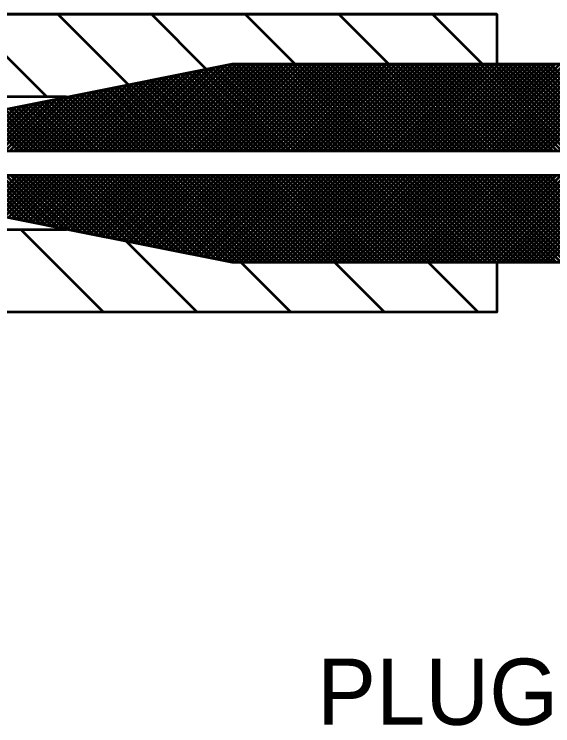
# Model space of a CAD drawing. Extents: x -32 to 824, y -6 to 538.
# Drawn here: x 183.94 to 203.45, y 439.33 to 465.12 of the extents above; entities that cross this region are included whole.
import ezdxf

# ---------------------------------------------------------------- set-up
doc = ezdxf.new("R2010")
doc.units = 0
doc.header["$LTSCALE"] = 1.1
doc.layers.add('1', color=7, linetype='Continuous', lineweight=53)

msp = doc.modelspace()

# ---------------------------------------------------------------- linework, layer by layer
at = {"layer": '1'}
for p, q in [((201.43, 465.121), (169.71, 465.121)), ((185.121, 462.121), (182.121, 465.121)), ((188.067, 462.569), (185.515, 465.121)), ((190.896, 463.134), (188.909, 465.121)), ((194.103, 463.321), (192.303, 465.121)), ((197.497, 463.321), (195.697, 465.121)), ((200.891, 463.321), (199.091, 465.121)), ((188.355, 460.171), (191.423, 463.24)), ((188.524, 460.171), (191.635, 463.282)), ((188.694, 460.171), (191.844, 463.321)), ((188.864, 460.171), (192.014, 463.321)), ((189.033, 460.171), (192.183, 463.321)), ((189.203, 460.171), (192.353, 463.321)), ((189.373, 460.171), (192.523, 463.321)), ((189.543, 460.171), (192.692, 463.321)), ((189.712, 460.171), (192.862, 463.321)), ((189.882, 460.171), (193.032, 463.321)), ((190.052, 460.171), (193.202, 463.321)), ((190.221, 460.171), (193.371, 463.321)), ((190.391, 460.171), (193.541, 463.321)), ((190.561, 460.171), (193.711, 463.321)), ((190.73, 460.171), (193.88, 463.321)), ((190.9, 460.171), (194.05, 463.321)), ((191.07, 460.171), (194.22, 463.321)), ((191.24, 460.171), (194.389, 463.321)), ((194.451, 460.171), (191.389, 463.233)), ((191.409, 460.171), (194.559, 463.321)), ((194.621, 460.171), (191.531, 463.261)), ((191.579, 460.171), (194.729, 463.321)), ((194.791, 460.171), (191.672, 463.29)), ((191.749, 460.171), (194.899, 463.321)), ((194.96, 460.171), (191.814, 463.318)), ((191.918, 460.171), (195.068, 463.321)), ((195.13, 460.171), (191.98, 463.321)), ((192.088, 460.171), (195.238, 463.321)), ((195.3, 460.171), (192.15, 463.321)), ((192.258, 460.171), (195.408, 463.321)), ((195.47, 460.171), (192.32, 463.321)), ((192.428, 460.171), (195.578, 463.321)), ((195.639, 460.171), (192.489, 463.321)), ((192.597, 460.171), (195.747, 463.321)), ((195.809, 460.171), (192.659, 463.321)), ((192.767, 460.171), (195.917, 463.321)), ((195.979, 460.171), (192.829, 463.321)), ((192.937, 460.171), (196.087, 463.321)), ((196.148, 460.171), (192.998, 463.321)), ((193.106, 460.171), (196.256, 463.321)), ((196.318, 460.171), (193.168, 463.321)), ((193.276, 460.171), (196.426, 463.321)), ((196.488, 460.171), (193.338, 463.321)), ((193.446, 460.171), (196.596, 463.321)), ((196.657, 460.171), (193.507, 463.321)), ((193.615, 460.171), (196.765, 463.321)), ((196.827, 460.171), (193.677, 463.321)), ((193.785, 460.171), (196.935, 463.321)), ((196.997, 460.171), (193.847, 463.321)), ((193.955, 460.171), (197.105, 463.321)), ((197.167, 460.171), (194.017, 463.321)), ((194.125, 460.171), (197.275, 463.321)), ((197.336, 460.171), (194.186, 463.321)), ((194.294, 460.171), (197.444, 463.321)), ((197.506, 460.171), (194.356, 463.321)), ((194.464, 460.171), (197.614, 463.321)), ((197.676, 460.171), (194.526, 463.321)), ((194.634, 460.171), (197.784, 463.321)), ((197.845, 460.171), (194.695, 463.321)), ((194.803, 460.171), (197.953, 463.321)), ((198.015, 460.171), (194.865, 463.321)), ((194.973, 460.171), (198.123, 463.321)), ((198.185, 460.171), (195.035, 463.321)), ((195.143, 460.171), (198.293, 463.321)), ((198.355, 460.171), (195.204, 463.321)), ((195.312, 460.171), (198.463, 463.321)), ((198.524, 460.171), (195.374, 463.321)), ((195.482, 460.171), (198.632, 463.321)), ((198.694, 460.171), (195.544, 463.321)), ((195.652, 460.171), (198.802, 463.321)), ((198.864, 460.171), (195.714, 463.321)), ((195.822, 460.171), (198.972, 463.321)), ((199.033, 460.171), (195.883, 463.321)), ((195.991, 460.171), (199.141, 463.321)), ((199.203, 460.171), (196.053, 463.321)), ((196.161, 460.171), (199.311, 463.321)), ((199.373, 460.171), (196.223, 463.321)), ((196.331, 460.171), (199.481, 463.321)), ((199.542, 460.171), (196.392, 463.321)), ((196.5, 460.171), (199.65, 463.321)), ((199.712, 460.171), (196.562, 463.321)), ((196.67, 460.171), (199.82, 463.321)), ((199.882, 460.171), (196.732, 463.321)), ((196.84, 460.171), (199.99, 463.321)), ((200.052, 460.171), (196.901, 463.321)), ((197.01, 460.171), (200.16, 463.321)), ((200.221, 460.171), (197.071, 463.321)), ((197.179, 460.171), (200.329, 463.321)), ((200.391, 460.171), (197.241, 463.321)), ((197.349, 460.171), (200.499, 463.321)), ((200.561, 460.171), (197.411, 463.321)), ((197.519, 460.171), (200.669, 463.321)), ((200.73, 460.171), (197.58, 463.321)), ((197.688, 460.171), (200.838, 463.321)), ((200.9, 460.171), (197.75, 463.321)), ((197.858, 460.171), (201.008, 463.321)), ((201.07, 460.171), (197.92, 463.321)), ((198.028, 460.171), (201.178, 463.321)), ((201.239, 460.171), (198.089, 463.321)), ((198.198, 460.171), (201.347, 463.321)), ((201.409, 460.171), (198.259, 463.321)), ((198.367, 460.171), (201.517, 463.321)), ((201.579, 460.171), (198.429, 463.321)), ((198.537, 460.171), (201.687, 463.321)), ((201.749, 460.171), (198.599, 463.321)), ((198.707, 460.171), (201.857, 463.321)), ((201.918, 460.171), (198.768, 463.321)), ((198.876, 460.171), (202.026, 463.321)), ((202.088, 460.171), (198.938, 463.321)), ((199.046, 460.171), (202.196, 463.321)), ((202.258, 460.171), (199.108, 463.321)), ((199.216, 460.171), (202.366, 463.321)), ((202.427, 460.171), (199.277, 463.321)), ((199.385, 460.171), (202.535, 463.321)), ((202.597, 460.171), (199.447, 463.321)), ((199.555, 460.171), (202.705, 463.321)), ((202.767, 460.171), (199.617, 463.321)), ((199.725, 460.171), (202.875, 463.321)), ((202.937, 460.171), (199.787, 463.321)), ((199.895, 460.171), (203.044, 463.321)), ((203.106, 460.171), (199.956, 463.321)), ((200.064, 460.171), (203.214, 463.321)), ((203.276, 460.171), (200.126, 463.321)), ((200.234, 460.171), (203.384, 463.321)), ((203.446, 460.171), (200.296, 463.321)), ((200.404, 460.171), (203.554, 463.321)), ((203.615, 460.171), (200.465, 463.321)), ((200.573, 460.171), (203.723, 463.321)), ((203.785, 460.171), (200.635, 463.321)), ((200.743, 460.171), (203.893, 463.321)), ((203.955, 460.171), (200.805, 463.321)), ((200.913, 460.171), (204.063, 463.321)), ((204.124, 460.171), (200.974, 463.321)), ((201.083, 460.171), (204.233, 463.321)), ((204.294, 460.171), (201.144, 463.321)), ((201.252, 460.171), (204.402, 463.321)), ((204.464, 460.171), (201.314, 463.321)), ((201.422, 460.171), (204.572, 463.321)), ((204.634, 460.171), (201.484, 463.321)), ((201.592, 460.171), (204.742, 463.321)), ((204.803, 460.171), (201.653, 463.321)), ((201.761, 460.171), (204.911, 463.321)), ((204.973, 460.171), (201.823, 463.321)), ((201.931, 460.171), (205.081, 463.321)), ((205.143, 460.171), (201.993, 463.321)), ((202.067, 463.275), (202.02, 463.321)), ((202.101, 460.171), (205.251, 463.321)), ((205.312, 460.171), (202.162, 463.321)), ((202.236, 463.275), (202.189, 463.321)), ((202.27, 460.171), (205.42, 463.321)), ((205.482, 460.171), (202.332, 463.321)), ((202.406, 463.275), (202.359, 463.321)), ((202.44, 460.171), (205.59, 463.321)), ((205.652, 460.171), (202.502, 463.321)), ((202.576, 463.275), (202.529, 463.321)), ((202.61, 460.171), (205.76, 463.321)), ((205.822, 460.171), (202.672, 463.321)), ((202.745, 463.275), (202.698, 463.321)), ((202.78, 460.171), (205.93, 463.321)), ((205.991, 460.171), (202.841, 463.321)), ((202.915, 463.275), (202.868, 463.321)), ((202.949, 460.171), (206.099, 463.321)), ((206.161, 460.171), (203.011, 463.321)), ((203.085, 463.275), (203.038, 463.321)), ((203.119, 460.171), (206.269, 463.321)), ((206.331, 460.171), (203.181, 463.321)), ((203.254, 463.275), (203.208, 463.321)), ((203.289, 460.171), (206.439, 463.321)), ((206.5, 460.171), (203.35, 463.321)), ((203.424, 463.275), (203.377, 463.321)), ((187.336, 460.171), (190.15, 462.985)), ((187.506, 460.171), (190.362, 463.028)), ((187.676, 460.171), (190.575, 463.07)), ((187.845, 460.171), (190.787, 463.113)), ((188.015, 460.171), (190.999, 463.155)), ((188.185, 460.171), (191.211, 463.197)), ((192.754, 460.171), (189.975, 462.95)), ((192.924, 460.171), (190.117, 462.978)), ((193.094, 460.171), (190.258, 463.007)), ((193.263, 460.171), (190.4, 463.035)), ((193.433, 460.171), (190.541, 463.063)), ((193.603, 460.171), (190.682, 463.092)), ((193.772, 460.171), (190.824, 463.12)), ((193.942, 460.171), (190.965, 463.148)), ((194.112, 460.171), (191.107, 463.177)), ((194.282, 460.171), (191.248, 463.205)), ((186.318, 460.171), (188.877, 462.731)), ((186.488, 460.171), (189.09, 462.773)), ((186.657, 460.171), (189.302, 462.816)), ((186.827, 460.171), (189.514, 462.858)), ((186.997, 460.171), (189.726, 462.9)), ((187.167, 460.171), (189.938, 462.943)), ((191.227, 460.171), (188.702, 462.696)), ((191.397, 460.171), (188.844, 462.724)), ((191.566, 460.171), (188.985, 462.752)), ((191.736, 460.171), (189.127, 462.781)), ((191.906, 460.171), (189.268, 462.809)), ((192.075, 460.171), (189.41, 462.837)), ((192.245, 460.171), (189.551, 462.865)), ((192.415, 460.171), (189.692, 462.894)), ((192.585, 460.171), (189.834, 462.922)), ((185.13, 460.171), (187.393, 462.434)), ((185.3, 460.171), (187.605, 462.476)), ((185.47, 460.171), (187.817, 462.519)), ((185.639, 460.171), (188.029, 462.561)), ((185.809, 460.171), (188.241, 462.603)), ((185.979, 460.171), (188.453, 462.646)), ((186.148, 460.171), (188.665, 462.688)), ((189.7, 460.171), (187.43, 462.441)), ((189.869, 460.171), (187.571, 462.469)), ((190.039, 460.171), (187.713, 462.498)), ((190.209, 460.171), (187.854, 462.526)), ((190.378, 460.171), (187.995, 462.554)), ((190.548, 460.171), (188.137, 462.583)), ((190.718, 460.171), (188.278, 462.611)), ((190.887, 460.171), (188.42, 462.639)), ((191.057, 460.171), (188.561, 462.667)), ((184.112, 460.171), (186.12, 462.179)), ((184.282, 460.171), (186.332, 462.222)), ((184.451, 460.171), (186.544, 462.264)), ((184.621, 460.171), (186.756, 462.307)), ((184.791, 460.171), (186.968, 462.349)), ((184.96, 460.171), (187.18, 462.391)), ((188.172, 460.171), (186.157, 462.187)), ((188.342, 460.171), (186.298, 462.215)), ((188.512, 460.171), (186.44, 462.243)), ((188.681, 460.171), (186.581, 462.271)), ((188.851, 460.171), (186.722, 462.3)), ((189.021, 460.171), (186.864, 462.328)), ((189.19, 460.171), (187.005, 462.356)), ((189.36, 460.171), (187.147, 462.385)), ((189.53, 460.171), (187.288, 462.413)), ((183.094, 460.171), (184.847, 461.925)), ((183.263, 460.171), (185.059, 461.967)), ((183.433, 460.171), (185.271, 462.01)), ((183.603, 460.171), (185.483, 462.052)), ((183.773, 460.171), (185.696, 462.094)), ((183.942, 460.171), (185.908, 462.137)), ((186.645, 460.171), (184.884, 461.932)), ((186.815, 460.171), (185.026, 461.96)), ((186.984, 460.171), (185.167, 461.989)), ((187.154, 460.171), (185.308, 462.017)), ((187.324, 460.171), (185.45, 462.045)), ((187.493, 460.171), (185.591, 462.073)), ((187.663, 460.171), (185.733, 462.102)), ((187.833, 460.171), (185.874, 462.13)), ((188.002, 460.171), (186.015, 462.158)), ((182.415, 460.171), (183.998, 461.755)), ((182.585, 460.171), (184.211, 461.797)), ((182.754, 460.171), (184.423, 461.84)), ((182.924, 460.171), (184.635, 461.882)), ((185.117, 460.171), (183.611, 461.678)), ((185.287, 460.171), (183.753, 461.706)), ((185.457, 460.171), (183.894, 461.734)), ((185.627, 460.171), (184.036, 461.762)), ((185.796, 460.171), (184.177, 461.791)), ((185.966, 460.171), (184.318, 461.819)), ((186.136, 460.171), (184.46, 461.847)), ((186.305, 460.171), (184.601, 461.876)), ((186.475, 460.171), (184.743, 461.904)), ((184.099, 460.171), (182.763, 461.508)), ((184.269, 460.171), (182.904, 461.536)), ((184.439, 460.171), (183.046, 461.564)), ((184.608, 460.171), (183.187, 461.593)), ((184.778, 460.171), (183.328, 461.621)), ((184.948, 460.171), (183.47, 461.649)), ((184.047, 457.678), (182.454, 459.271)), ((184.259, 457.636), (182.623, 459.271)), ((182.73, 457.941), (184.06, 459.271)), ((184.471, 457.593), (182.793, 459.271)), ((182.872, 457.913), (184.23, 459.271)), ((184.683, 457.551), (182.963, 459.271)), ((183.013, 457.885), (184.4, 459.271)), ((184.895, 457.508), (183.132, 459.271)), ((183.155, 457.856), (184.57, 459.271)), ((183.296, 457.828), (184.739, 459.271)), ((185.108, 457.466), (183.302, 459.271)), ((183.438, 457.8), (184.909, 459.271)), ((185.32, 457.423), (183.472, 459.271)), ((183.579, 457.772), (185.079, 459.271)), ((185.532, 457.381), (183.642, 459.271)), ((183.72, 457.743), (185.248, 459.271)), ((185.744, 457.339), (183.811, 459.271)), ((183.862, 457.715), (185.418, 459.271)), ((185.956, 457.296), (183.981, 459.271)), ((184.003, 457.687), (185.588, 459.271)), ((184.145, 457.658), (185.758, 459.271)), ((186.168, 457.254), (184.151, 459.271)), ((184.286, 457.63), (185.927, 459.271)), ((186.38, 457.211), (184.32, 459.271)), ((184.427, 457.602), (186.097, 459.271)), ((186.593, 457.169), (184.49, 459.271)), ((184.569, 457.574), (186.267, 459.271)), ((186.805, 457.126), (184.66, 459.271)), ((184.71, 457.545), (186.436, 459.271)), ((187.017, 457.084), (184.829, 459.271)), ((184.852, 457.517), (186.606, 459.271)), ((184.993, 457.489), (186.776, 459.271)), ((187.229, 457.042), (184.999, 459.271)), ((185.135, 457.46), (186.945, 459.271)), ((187.441, 456.999), (185.169, 459.271)), ((185.276, 457.432), (187.115, 459.271)), ((187.653, 456.957), (185.339, 459.271)), ((185.417, 457.404), (187.285, 459.271)), ((187.865, 456.914), (185.508, 459.271)), ((185.559, 457.376), (187.454, 459.271)), ((188.077, 456.872), (185.678, 459.271)), ((185.7, 457.347), (187.624, 459.271)), ((185.842, 457.319), (187.794, 459.271)), ((188.29, 456.829), (185.848, 459.271)), ((185.983, 457.291), (187.964, 459.271)), ((188.502, 456.787), (186.017, 459.271)), ((186.125, 457.262), (188.133, 459.271)), ((188.714, 456.745), (186.187, 459.271)), ((186.266, 457.234), (188.303, 459.271)), ((188.926, 456.702), (186.357, 459.271)), ((186.407, 457.206), (188.473, 459.271)), ((189.138, 456.66), (186.526, 459.271)), ((186.549, 457.178), (188.643, 459.271)), ((186.69, 457.149), (188.812, 459.271)), ((189.35, 456.617), (186.696, 459.271)), ((186.832, 457.121), (188.982, 459.271)), ((189.562, 456.575), (186.866, 459.271)), ((186.973, 457.093), (189.152, 459.271)), ((189.775, 456.533), (187.036, 459.271)), ((187.115, 457.065), (189.321, 459.271)), ((189.987, 456.49), (187.205, 459.271)), ((187.256, 457.036), (189.491, 459.271)), ((190.199, 456.448), (187.375, 459.271)), ((187.397, 457.008), (189.661, 459.271)), ((187.539, 456.98), (189.83, 459.271)), ((190.411, 456.405), (187.545, 459.271)), ((187.68, 456.951), (190, 459.271)), ((190.623, 456.363), (187.715, 459.271)), ((187.822, 456.923), (190.17, 459.271)), ((190.835, 456.32), (187.884, 459.271)), ((187.963, 456.895), (190.34, 459.271)), ((191.047, 456.278), (188.054, 459.271)), ((188.104, 456.867), (190.509, 459.271)), ((191.259, 456.236), (188.224, 459.271)), ((188.246, 456.838), (190.679, 459.271)), ((188.387, 456.81), (190.849, 459.271)), ((191.472, 456.193), (188.393, 459.271)), ((188.529, 456.782), (191.018, 459.271)), ((191.684, 456.151), (188.563, 459.271)), ((188.67, 456.753), (191.188, 459.271)), ((191.883, 456.121), (188.733, 459.271)), ((188.811, 456.725), (191.358, 459.271)), ((192.052, 456.121), (188.902, 459.271)), ((188.953, 456.697), (191.528, 459.271)), ((192.222, 456.121), (189.072, 459.271)), ((189.094, 456.668), (191.697, 459.271)), ((189.236, 456.64), (191.867, 459.271)), ((192.392, 456.121), (189.242, 459.271)), ((189.377, 456.612), (192.037, 459.271)), ((192.561, 456.121), (189.412, 459.271)), ((189.519, 456.584), (192.206, 459.271)), ((192.731, 456.121), (189.581, 459.271)), ((189.66, 456.555), (192.376, 459.271)), ((192.901, 456.121), (189.751, 459.271)), ((189.802, 456.527), (192.546, 459.271)), ((193.071, 456.121), (189.921, 459.271)), ((189.943, 456.499), (192.715, 459.271)), ((190.084, 456.471), (192.885, 459.271)), ((193.24, 456.121), (190.09, 459.271)), ((190.226, 456.442), (193.055, 459.271)), ((193.41, 456.121), (190.26, 459.271)), ((190.367, 456.414), (193.225, 459.271)), ((193.58, 456.121), (190.43, 459.271)), ((190.509, 456.386), (193.394, 459.271)), ((193.75, 456.121), (190.6, 459.271)), ((190.65, 456.357), (193.564, 459.271)), ((193.919, 456.121), (190.769, 459.271)), ((190.791, 456.329), (193.734, 459.271)), ((190.933, 456.301), (193.903, 459.271)), ((194.089, 456.121), (190.939, 459.271)), ((191.074, 456.273), (194.073, 459.271)), ((194.259, 456.121), (191.109, 459.271)), ((191.216, 456.244), (194.243, 459.271)), ((194.428, 456.121), (191.278, 459.271)), ((191.357, 456.216), (194.413, 459.271)), ((194.598, 456.121), (191.448, 459.271)), ((191.499, 456.188), (194.582, 459.271)), ((194.768, 456.121), (191.618, 459.271)), ((191.64, 456.159), (194.752, 459.271)), ((191.781, 456.131), (194.922, 459.271)), ((194.937, 456.121), (191.787, 459.271)), ((191.941, 456.121), (195.091, 459.271)), ((195.107, 456.121), (191.957, 459.271)), ((192.111, 456.121), (195.261, 459.271)), ((195.277, 456.121), (192.127, 459.271)), ((192.281, 456.121), (195.431, 459.271)), ((195.447, 456.121), (192.297, 459.271)), ((192.45, 456.121), (195.6, 459.271)), ((195.616, 456.121), (192.466, 459.271)), ((192.62, 456.121), (195.77, 459.271)), ((195.786, 456.121), (192.636, 459.271)), ((192.79, 456.121), (195.94, 459.271)), ((195.956, 456.121), (192.806, 459.271)), ((192.96, 456.121), (196.109, 459.271)), ((196.125, 456.121), (192.975, 459.271)), ((193.129, 456.121), (196.279, 459.271)), ((196.295, 456.121), (193.145, 459.271)), ((193.299, 456.121), (196.449, 459.271)), ((196.465, 456.121), (193.315, 459.271)), ((193.469, 456.121), (196.619, 459.271)), ((196.635, 456.121), (193.484, 459.271)), ((193.638, 456.121), (196.788, 459.271)), ((196.804, 456.121), (193.654, 459.271)), ((193.808, 456.121), (196.958, 459.271)), ((196.974, 456.121), (193.824, 459.271)), ((193.978, 456.121), (197.128, 459.271)), ((197.144, 456.121), (193.994, 459.271)), ((194.148, 456.121), (197.298, 459.271)), ((197.313, 456.121), (194.163, 459.271)), ((194.317, 456.121), (197.467, 459.271)), ((197.483, 456.121), (194.333, 459.271)), ((194.487, 456.121), (197.637, 459.271)), ((197.653, 456.121), (194.503, 459.271)), ((194.657, 456.121), (197.807, 459.271)), ((197.822, 456.121), (194.672, 459.271)), ((194.826, 456.121), (197.976, 459.271)), ((197.992, 456.121), (194.842, 459.271)), ((194.996, 456.121), (198.146, 459.271)), ((198.162, 456.121), (195.012, 459.271)), ((195.166, 456.121), (198.316, 459.271)), ((198.332, 456.121), (195.181, 459.271)), ((195.335, 456.121), (198.485, 459.271)), ((198.501, 456.121), (195.351, 459.271)), ((195.505, 456.121), (198.655, 459.271)), ((198.671, 456.121), (195.521, 459.271)), ((195.675, 456.121), (198.825, 459.271)), ((198.841, 456.121), (195.691, 459.271)), ((195.845, 456.121), (198.995, 459.271)), ((199.01, 456.121), (195.86, 459.271)), ((196.014, 456.121), (199.164, 459.271)), ((199.18, 456.121), (196.03, 459.271)), ((196.184, 456.121), (199.334, 459.271)), ((199.35, 456.121), (196.2, 459.271)), ((196.354, 456.121), (199.504, 459.271)), ((199.52, 456.121), (196.37, 459.271)), ((196.523, 456.121), (199.673, 459.271)), ((199.689, 456.121), (196.539, 459.271)), ((196.693, 456.121), (199.843, 459.271)), ((199.859, 456.121), (196.709, 459.271)), ((196.863, 456.121), (200.013, 459.271)), ((200.029, 456.121), (196.879, 459.271)), ((197.032, 456.121), (200.183, 459.271)), ((200.198, 456.121), (197.048, 459.271)), ((197.202, 456.121), (200.352, 459.271)), ((200.368, 456.121), (197.218, 459.271)), ((197.372, 456.121), (200.522, 459.271)), ((200.538, 456.121), (197.388, 459.271)), ((197.542, 456.121), (200.692, 459.271)), ((200.707, 456.121), (197.557, 459.271)), ((197.711, 456.121), (200.861, 459.271)), ((200.877, 456.121), (197.727, 459.271)), ((197.881, 456.121), (201.031, 459.271)), ((201.047, 456.121), (197.897, 459.271)), ((198.051, 456.121), (201.201, 459.271)), ((201.216, 456.121), (198.067, 459.271)), ((198.22, 456.121), (201.37, 459.271)), ((201.386, 456.121), (198.236, 459.271)), ((198.39, 456.121), (201.54, 459.271)), ((201.556, 456.121), (198.406, 459.271)), ((198.56, 456.121), (201.71, 459.271)), ((201.726, 456.121), (198.576, 459.271)), ((198.73, 456.121), (201.88, 459.271)), ((201.895, 456.121), (198.745, 459.271)), ((198.899, 456.121), (202.049, 459.271)), ((202.065, 456.121), (198.915, 459.271)), ((199.069, 456.121), (202.219, 459.271)), ((202.235, 456.121), (199.085, 459.271)), ((199.239, 456.121), (202.389, 459.271)), ((202.405, 456.121), (199.255, 459.271)), ((199.408, 456.121), (202.558, 459.271)), ((202.574, 456.121), (199.424, 459.271)), ((199.578, 456.121), (202.728, 459.271)), ((202.744, 456.121), (199.594, 459.271)), ((199.748, 456.121), (202.898, 459.271)), ((202.914, 456.121), (199.764, 459.271)), ((199.918, 456.121), (203.068, 459.271)), ((203.083, 456.121), (199.933, 459.271)), ((200.087, 456.121), (203.237, 459.271)), ((203.253, 456.121), (200.103, 459.271)), ((200.257, 456.121), (203.407, 459.271)), ((203.423, 456.121), (200.273, 459.271)), ((200.427, 456.121), (203.577, 459.271)), ((203.592, 456.121), (200.442, 459.271)), ((200.596, 456.121), (203.746, 459.271)), ((203.762, 456.121), (200.612, 459.271)), ((200.766, 456.121), (203.916, 459.271)), ((203.932, 456.121), (200.782, 459.271)), ((200.936, 456.121), (204.086, 459.271)), ((204.102, 456.121), (200.952, 459.271)), ((201.105, 456.121), (204.255, 459.271)), ((204.271, 456.121), (201.121, 459.271)), ((201.275, 456.121), (204.425, 459.271)), ((204.441, 456.121), (201.291, 459.271)), ((201.445, 456.121), (204.595, 459.271)), ((204.611, 456.121), (201.461, 459.271)), ((201.615, 456.121), (204.764, 459.271)), ((204.78, 456.121), (201.63, 459.271)), ((201.784, 456.121), (204.934, 459.271)), ((204.95, 456.121), (201.8, 459.271)), ((201.954, 456.121), (205.104, 459.271)), ((205.12, 456.121), (201.97, 459.271)), ((202.124, 456.121), (205.274, 459.271)), ((205.289, 456.121), (202.139, 459.271)), ((202.293, 456.121), (205.443, 459.271)), ((205.459, 456.121), (202.309, 459.271)), ((202.463, 456.121), (205.613, 459.271)), ((205.629, 456.121), (202.479, 459.271)), ((202.633, 456.121), (205.783, 459.271)), ((205.799, 456.121), (202.649, 459.271)), ((202.802, 456.121), (205.952, 459.271)), ((205.968, 456.121), (202.818, 459.271)), ((202.972, 456.121), (206.122, 459.271)), ((206.138, 456.121), (202.988, 459.271)), ((203.142, 456.121), (206.292, 459.271)), ((206.308, 456.121), (203.158, 459.271)), ((203.312, 456.121), (206.462, 459.271)), ((206.477, 456.121), (203.327, 459.271)), ((187.174, 454.321), (184.174, 457.321)), ((190.568, 454.321), (188.002, 456.887)), ((193.962, 454.321), (192.162, 456.121)), ((197.356, 454.321), (195.556, 456.121)), ((197.936, 456.121), (197.978, 456.163)), ((198.105, 456.121), (198.147, 456.163)), ((198.275, 456.121), (198.317, 456.163)), ((198.615, 456.121), (198.656, 456.163)), ((198.784, 456.121), (198.826, 456.163)), ((200.75, 454.321), (198.95, 456.121)), ((198.954, 456.121), (198.996, 456.163)), ((199.293, 456.121), (199.335, 456.163)), ((199.463, 456.121), (199.505, 456.163)), ((199.633, 456.121), (199.675, 456.163)), ((199.802, 456.121), (199.844, 456.163)), ((199.972, 456.121), (200.014, 456.163)), ((200.142, 456.121), (200.184, 456.163)), ((200.312, 456.121), (200.353, 456.163)), ((200.481, 456.121), (200.523, 456.163)), ((200.651, 456.121), (200.693, 456.163)), ((200.99, 456.121), (201.032, 456.163)), ((201.16, 456.121), (201.202, 456.163)), ((201.33, 456.121), (201.372, 456.163)), ((201.5, 456.121), (201.541, 456.163)), ((201.583, 456.121), (201.541, 456.163)), ((201.669, 456.121), (201.711, 456.163)), ((201.753, 456.121), (201.711, 456.163)), ((201.839, 456.121), (201.881, 456.163)), ((201.922, 456.121), (201.881, 456.163)), ((202.009, 456.121), (202.05, 456.163)), ((202.092, 456.121), (202.05, 456.163)), ((202.178, 456.121), (202.22, 456.163)), ((202.262, 456.121), (202.22, 456.163)), ((202.431, 456.121), (202.39, 456.163)), ((202.518, 456.121), (202.56, 456.163)), ((202.601, 456.121), (202.559, 456.163)), ((202.687, 456.121), (202.729, 456.163)), ((202.771, 456.121), (202.729, 456.163)), ((202.857, 456.121), (202.899, 456.163)), ((202.941, 456.121), (202.899, 456.163)), ((203.027, 456.121), (203.069, 456.163)), ((203.11, 456.121), (203.069, 456.163)), ((203.197, 456.121), (203.238, 456.163)), ((203.28, 456.121), (203.238, 456.163)), ((203.366, 456.121), (203.408, 456.163)), ((203.45, 456.121), (203.408, 456.163)), ((201.43, 454.321), (169.245, 454.321))]:
    msp.add_line(p, q, dxfattribs=at)
for points in [[(169.93, 460.621), (159.13, 460.621), (159.13, 461.221), (160.93, 462.571), (160.93, 462.121), (168.73, 462.121), (168.73, 463.021), (168.73, 465.121), (201.43, 465.121), (201.43, 463.321)], [(185.83, 462.121), (173.23, 462.121), (172.03, 460.621), (170.53, 460.621)], [(170.53, 458.821), (172.03, 458.821), (173.23, 457.321), (185.83, 457.321)], [(201.43, 456.121), (201.43, 454.321), (168.73, 454.321)]]:
    msp.add_lwpolyline(points, dxfattribs=at)
for points in [[(179.83, 458.521), (179.83, 460.921), (191.83, 463.321), (201.43, 463.321), (216.43, 463.321), (216.43, 460.921), (216.43, 458.521), (216.43, 456.121), (201.43, 456.121), (191.83, 456.121), (185.83, 457.321)], [(180.43, 459.271), (180.43, 460.171), (215.83, 460.171), (215.83, 459.271)]]:
    msp.add_lwpolyline(points, close=True, dxfattribs=at)

# ---------------------------------------------------------------- texts
msp.add_text('PLUG', height=2.4, dxfattribs=at).set_placement((194.909, 439.364))

doc.saveas('drawing.dxf')
